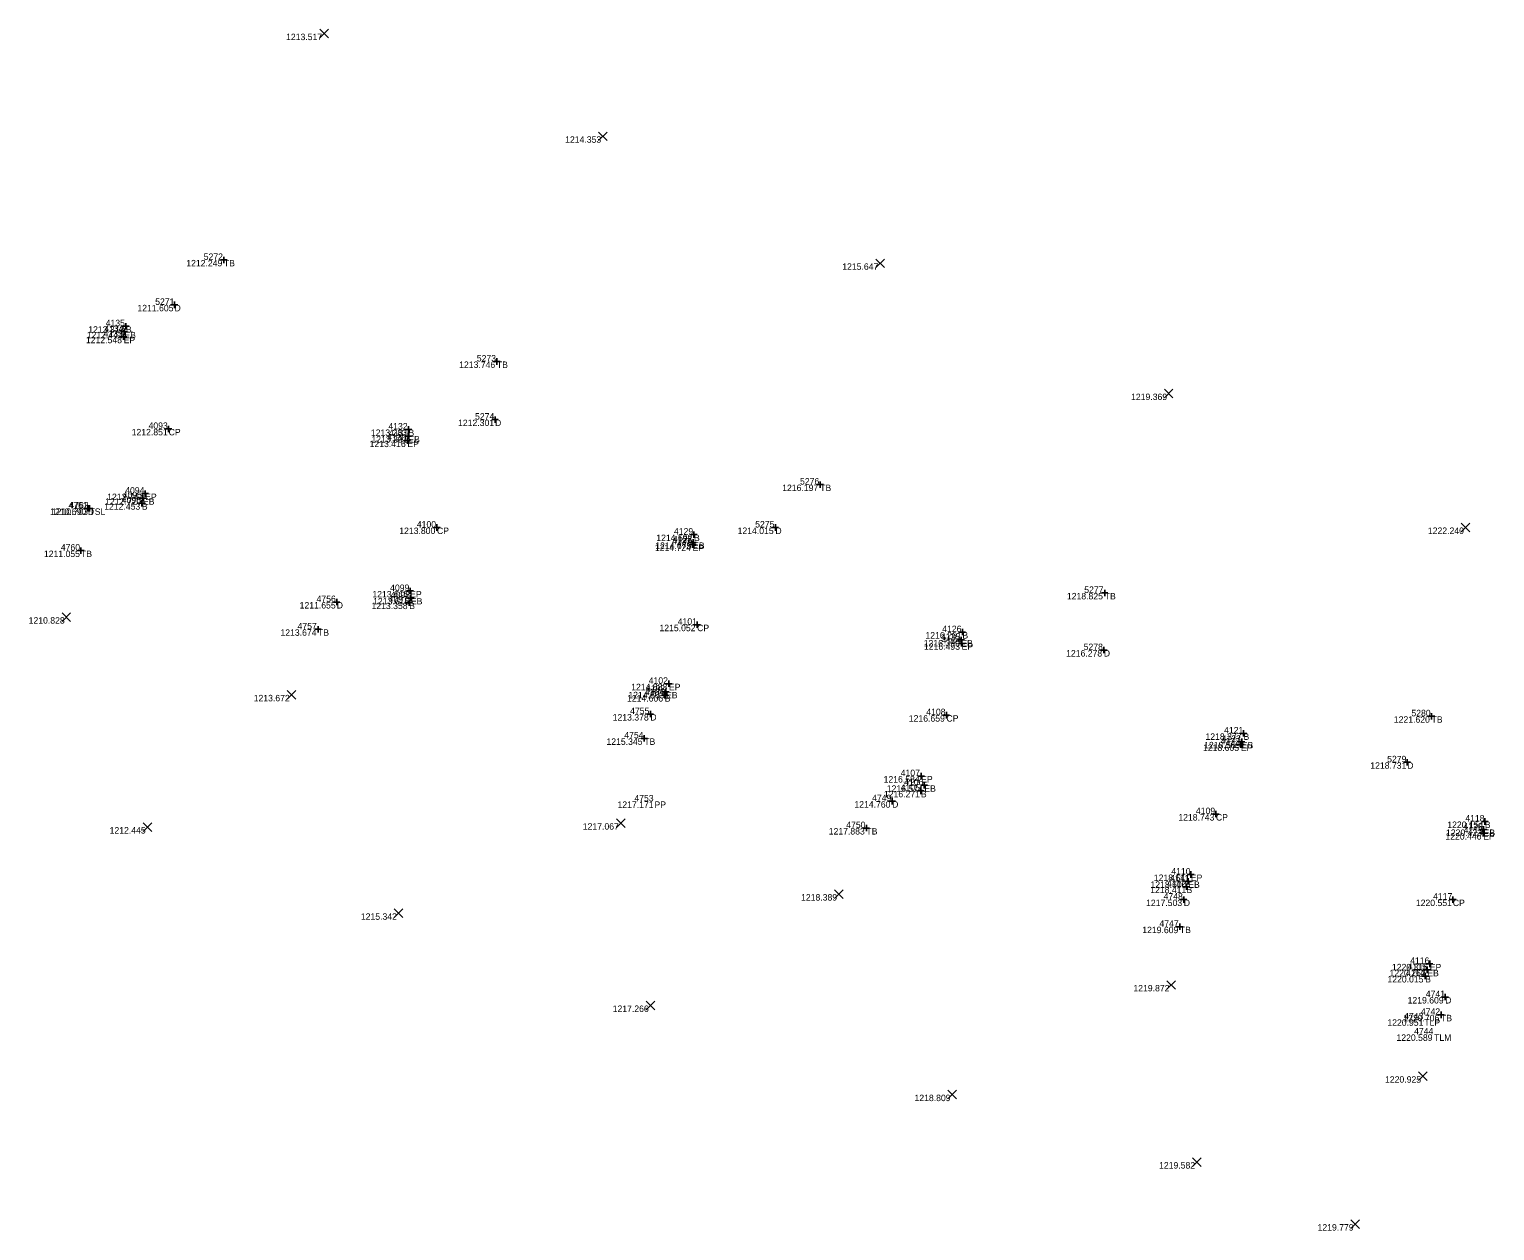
# Model space of a CAD drawing. Extents: x 2044997 to 2050342, y 455233 to 458054.
# Drawn here: x 2048396.8 to 2048623.5, y 456585.3 to 456771.2 of the extents above; entities that cross this region are included whole.
import ezdxf

# ---------------------------------------------------------------- set-up
doc = ezdxf.new("R2010")
doc.units = 0
for name, color, linetype in [('SV_X_Random_Point', 7, 'Continuous'), ('SV_X_Shot_Marker', 7, 'Continuous'), ('SV_X_Text_Comment', 7, 'Continuous'), ('SV_X_Text_Elevation', 7, 'Continuous'), ('SV_X_Text_Name', 7, 'Continuous')]:
    doc.layers.add(name, color=color, linetype=linetype)

msp = doc.modelspace()

# ---------------------------------------------------------------- linework, layer by layer
at = {"layer": 'SV_X_Random_Point'}
for p, q in [((2048441.72, 456769.84), (2048443.05, 456771.17)), ((2048441.72, 456771.17), (2048443.05, 456769.84)), ((2048484.85, 456753.95), (2048486.18, 456755.28)), ((2048484.85, 456755.28), (2048486.18, 456753.95)), ((2048527.78, 456734.31), (2048529.11, 456735.64)), ((2048527.78, 456735.64), (2048529.11, 456734.31)), ((2048572.4, 456714.15), (2048573.73, 456715.49)), ((2048572.4, 456715.49), (2048573.73, 456714.15)), ((2048618.34, 456693.45), (2048619.67, 456694.78)), ((2048618.34, 456694.78), (2048619.67, 456693.45)), ((2048401.85, 456679.57), (2048403.18, 456680.9)), ((2048401.85, 456680.9), (2048403.18, 456679.57)), ((2048436.67, 456667.55), (2048438, 456668.89)), ((2048436.67, 456668.89), (2048438, 456667.55)), ((2048487.63, 456647.71), (2048488.97, 456649.04)), ((2048487.63, 456649.04), (2048488.97, 456647.71)), ((2048414.39, 456647.1), (2048415.72, 456648.44)), ((2048414.39, 456648.44), (2048415.72, 456647.1)), ((2048521.35, 456636.73), (2048522.68, 456638.06)), ((2048521.35, 456638.06), (2048522.68, 456636.73)), ((2048453.24, 456633.77), (2048454.58, 456635.1)), ((2048453.24, 456635.1), (2048454.58, 456633.77)), ((2048572.78, 456622.68), (2048574.11, 456624.01)), ((2048572.78, 456624.01), (2048574.11, 456622.68)), ((2048492.21, 456619.5), (2048493.54, 456620.83)), ((2048492.21, 456620.83), (2048493.54, 456619.5)), ((2048611.72, 456608.56), (2048613.06, 456609.9)), ((2048611.72, 456609.9), (2048613.06, 456608.56)), ((2048538.89, 456605.71), (2048540.22, 456607.05)), ((2048538.89, 456607.05), (2048540.22, 456605.71)), ((2048576.74, 456595.28), (2048578.08, 456596.62)), ((2048576.74, 456596.62), (2048578.08, 456595.28)), ((2048601.25, 456585.68), (2048602.59, 456587.02)), ((2048601.25, 456587.02), (2048602.59, 456585.68))]:
    msp.add_line(p, q, dxfattribs=at)
at = {"layer": 'SV_X_Shot_Marker'}
for p, q in [((2048426.39, 456735.5), (2048427.39, 456735.5)), ((2048426.89, 456736), (2048426.89, 456735)), ((2048426.89, 456735.5), (2048426.89, 456735.5)), ((2048418.75, 456728.55), (2048419.75, 456728.55)), ((2048419.25, 456729.05), (2048419.25, 456728.05)), ((2048419.25, 456728.55), (2048419.25, 456728.55)), ((2048410.88, 456723.62), (2048411.88, 456723.62)), ((2048410.99, 456724.38), (2048411.99, 456724.38)), ((2048411.23, 456725.24), (2048412.23, 456725.24)), ((2048411.38, 456724.12), (2048411.38, 456723.12)), ((2048411.38, 456723.62), (2048411.38, 456723.62)), ((2048411.49, 456724.88), (2048411.49, 456723.88)), ((2048411.49, 456724.38), (2048411.49, 456724.38)), ((2048411.73, 456725.74), (2048411.73, 456724.74)), ((2048411.73, 456725.24), (2048411.73, 456725.24)), ((2048468.63, 456719.79), (2048469.63, 456719.79)), ((2048469.13, 456720.29), (2048469.13, 456719.29)), ((2048469.13, 456719.79), (2048469.13, 456719.79)), ((2048468.34, 456710.8), (2048469.34, 456710.8)), ((2048468.84, 456711.3), (2048468.84, 456710.3)), ((2048468.84, 456710.8), (2048468.84, 456710.8)), ((2048417.84, 456709.36), (2048418.84, 456709.36)), ((2048418.34, 456709.86), (2048418.34, 456708.86)), ((2048418.34, 456709.36), (2048418.34, 456709.36)), ((2048454.92, 456708.25), (2048455.92, 456708.25)), ((2048454.95, 456709.27), (2048455.95, 456709.27)), ((2048455.28, 456708.05), (2048455.28, 456707.05)), ((2048455.42, 456708.75), (2048455.42, 456707.75)), ((2048455.42, 456708.25), (2048455.42, 456708.25)), ((2048455.45, 456709.77), (2048455.45, 456708.77)), ((2048455.45, 456709.27), (2048455.45, 456709.27)), ((2048454.78, 456707.55), (2048455.78, 456707.55)), ((2048455.28, 456707.55), (2048455.28, 456707.55)), ((2048519.15, 456701.25), (2048519.15, 456700.25)), ((2048413.86, 456698.64), (2048414.86, 456698.64)), ((2048414.21, 456699.35), (2048415.21, 456699.35)), ((2048414.36, 456699.14), (2048414.36, 456698.14)), ((2048414.36, 456698.64), (2048414.36, 456698.64)), ((2048414.71, 456699.85), (2048414.71, 456698.85)), ((2048414.71, 456699.35), (2048414.71, 456699.35)), ((2048518.65, 456700.75), (2048519.65, 456700.75)), ((2048519.15, 456700.75), (2048519.15, 456700.75)), ((2048405.34, 456697.06), (2048406.34, 456697.06)), ((2048405.59, 456697.06), (2048406.59, 456697.06)), ((2048405.84, 456697.56), (2048405.84, 456696.56)), ((2048405.84, 456697.06), (2048405.84, 456697.06)), ((2048406.09, 456697.56), (2048406.09, 456696.56)), ((2048406.09, 456697.06), (2048406.09, 456697.06)), ((2048413.7, 456697.87), (2048414.7, 456697.87)), ((2048414.2, 456698.37), (2048414.2, 456697.37)), ((2048414.2, 456697.87), (2048414.2, 456697.87)), ((2048459.36, 456694.1), (2048460.36, 456694.1)), ((2048459.86, 456694.6), (2048459.86, 456693.6)), ((2048459.86, 456694.1), (2048459.86, 456694.1)), ((2048511.72, 456694.11), (2048512.72, 456694.11)), ((2048512.22, 456694.61), (2048512.22, 456693.61)), ((2048512.22, 456694.11), (2048512.22, 456694.11)), ((2048499.12, 456693.01), (2048500.12, 456693.01)), ((2048499.39, 456691.99), (2048499.39, 456690.99)), ((2048499.48, 456692.3), (2048499.48, 456691.3)), ((2048499.62, 456693.51), (2048499.62, 456692.51)), ((2048499.62, 456693.01), (2048499.62, 456693.01)), ((2048404.28, 456690.54), (2048405.28, 456690.54)), ((2048404.78, 456691.04), (2048404.78, 456690.04)), ((2048404.78, 456690.54), (2048404.78, 456690.54)), ((2048498.89, 456691.49), (2048499.89, 456691.49)), ((2048498.98, 456691.8), (2048499.98, 456691.8)), ((2048499.39, 456691.49), (2048499.39, 456691.49)), ((2048499.48, 456691.8), (2048499.48, 456691.8)), ((2048444.35, 456683.08), (2048444.35, 456682.08)), ((2048455.21, 456684.29), (2048456.21, 456684.29)), ((2048455.32, 456683.2), (2048456.32, 456683.2)), ((2048455.56, 456682.99), (2048455.56, 456681.99)), ((2048455.71, 456684.79), (2048455.71, 456683.79)), ((2048455.71, 456684.29), (2048455.71, 456684.29)), ((2048455.82, 456683.7), (2048455.82, 456682.7)), ((2048455.82, 456683.2), (2048455.82, 456683.2)), ((2048562.67, 456683.99), (2048563.67, 456683.99)), ((2048563.17, 456684.49), (2048563.17, 456683.49)), ((2048563.17, 456683.99), (2048563.17, 456683.99)), ((2048443.85, 456682.58), (2048444.85, 456682.58)), ((2048444.35, 456682.58), (2048444.35, 456682.58)), ((2048455.06, 456682.49), (2048456.06, 456682.49)), ((2048455.56, 456682.49), (2048455.56, 456682.49)), ((2048440.95, 456678.36), (2048441.95, 456678.36)), ((2048441.45, 456678.86), (2048441.45, 456677.86)), ((2048441.45, 456678.36), (2048441.45, 456678.36)), ((2048499.61, 456679.07), (2048500.61, 456679.07)), ((2048500.11, 456679.57), (2048500.11, 456678.57)), ((2048500.11, 456679.07), (2048500.11, 456679.07)), ((2048541.15, 456678.43), (2048541.15, 456677.43)), ((2048540.48, 456676.72), (2048541.48, 456676.72)), ((2048540.53, 456676.19), (2048541.53, 456676.19)), ((2048540.65, 456677.93), (2048541.65, 456677.93)), ((2048540.98, 456677.22), (2048540.98, 456676.22)), ((2048540.98, 456676.72), (2048540.98, 456676.72)), ((2048541.03, 456676.69), (2048541.03, 456675.69)), ((2048541.03, 456676.19), (2048541.03, 456676.19)), ((2048541.15, 456677.93), (2048541.15, 456677.93)), ((2048562.53, 456675.15), (2048563.53, 456675.15)), ((2048563.03, 456675.65), (2048563.03, 456674.65)), ((2048563.03, 456675.15), (2048563.03, 456675.15)), ((2048495.24, 456669.94), (2048496.24, 456669.94)), ((2048495.29, 456669.19), (2048495.29, 456668.19)), ((2048495.74, 456670.44), (2048495.74, 456669.44)), ((2048495.74, 456669.94), (2048495.74, 456669.94)), ((2048494.6, 456668.18), (2048495.6, 456668.18)), ((2048494.79, 456668.69), (2048495.79, 456668.69)), ((2048495.1, 456668.68), (2048495.1, 456667.68)), ((2048495.1, 456668.18), (2048495.1, 456668.18)), ((2048495.29, 456668.69), (2048495.29, 456668.69)), ((2048492.37, 456665.25), (2048493.37, 456665.25)), ((2048492.87, 456665.75), (2048492.87, 456664.75)), ((2048492.87, 456665.25), (2048492.87, 456665.25)), ((2048538.18, 456665.08), (2048539.18, 456665.08)), ((2048538.68, 456665.58), (2048538.68, 456664.58)), ((2048538.68, 456665.08), (2048538.68, 456665.08)), ((2048613.24, 456664.91), (2048614.24, 456664.91)), ((2048613.74, 456665.41), (2048613.74, 456664.41)), ((2048613.74, 456664.91), (2048613.74, 456664.91)), ((2048584.64, 456662.76), (2048584.64, 456661.76)), ((2048491.43, 456661.49), (2048492.43, 456661.49)), ((2048491.93, 456661.99), (2048491.93, 456660.99)), ((2048491.93, 456661.49), (2048491.93, 456661.49)), ((2048583.73, 456660.55), (2048584.73, 456660.55)), ((2048583.87, 456660.95), (2048584.87, 456660.95)), ((2048584.14, 456662.26), (2048585.14, 456662.26)), ((2048584.23, 456661.05), (2048584.23, 456660.05)), ((2048584.23, 456660.55), (2048584.23, 456660.55)), ((2048584.37, 456661.45), (2048584.37, 456660.45)), ((2048584.37, 456660.95), (2048584.37, 456660.95)), ((2048584.64, 456662.26), (2048584.64, 456662.26)), ((2048609.97, 456658.29), (2048609.97, 456657.29)), ((2048534.27, 456655.66), (2048535.27, 456655.66)), ((2048534.77, 456656.16), (2048534.77, 456655.16)), ((2048534.77, 456655.66), (2048534.77, 456655.66)), ((2048609.47, 456657.79), (2048610.47, 456657.79)), ((2048609.97, 456657.79), (2048609.97, 456657.79)), ((2048534.23, 456653.37), (2048535.23, 456653.37)), ((2048534.73, 456653.87), (2048534.73, 456652.87)), ((2048534.73, 456653.37), (2048534.73, 456653.37)), ((2048534.76, 456654.23), (2048535.76, 456654.23)), ((2048535.26, 456654.73), (2048535.26, 456653.73)), ((2048535.26, 456654.23), (2048535.26, 456654.23)), ((2048529.78, 456651.78), (2048530.78, 456651.78)), ((2048530.28, 456652.28), (2048530.28, 456651.28)), ((2048530.28, 456651.78), (2048530.28, 456651.78)), ((2048579.88, 456649.78), (2048580.88, 456649.78)), ((2048580.38, 456650.28), (2048580.38, 456649.28)), ((2048580.38, 456649.78), (2048580.38, 456649.78)), ((2048621.98, 456649.13), (2048621.98, 456648.13)), ((2048525.8, 456647.62), (2048526.8, 456647.62)), ((2048526.3, 456648.12), (2048526.3, 456647.12)), ((2048526.3, 456647.62), (2048526.3, 456647.62)), ((2048621.22, 456646.83), (2048622.22, 456646.83)), ((2048621.29, 456647.4), (2048622.29, 456647.4)), ((2048621.48, 456648.63), (2048622.48, 456648.63)), ((2048621.72, 456647.33), (2048621.72, 456646.33)), ((2048621.72, 456646.83), (2048621.72, 456646.83)), ((2048621.79, 456647.9), (2048621.79, 456646.9)), ((2048621.79, 456647.4), (2048621.79, 456647.4)), ((2048621.98, 456648.63), (2048621.98, 456648.63)), ((2048575.99, 456640.43), (2048576.99, 456640.43)), ((2048576.09, 456639.87), (2048576.09, 456638.87)), ((2048576.49, 456640.93), (2048576.49, 456639.93)), ((2048576.49, 456640.43), (2048576.49, 456640.43)), ((2048575.32, 456638.55), (2048576.32, 456638.55)), ((2048575.59, 456639.37), (2048576.59, 456639.37)), ((2048575.82, 456639.05), (2048575.82, 456638.05)), ((2048575.82, 456638.55), (2048575.82, 456638.55)), ((2048576.09, 456639.37), (2048576.09, 456639.37)), ((2048574.9, 456636.55), (2048575.9, 456636.55)), ((2048575.4, 456637.05), (2048575.4, 456636.05)), ((2048575.4, 456636.55), (2048575.4, 456636.55)), ((2048616.53, 456636.55), (2048617.53, 456636.55)), ((2048617.03, 456637.05), (2048617.03, 456636.05)), ((2048617.03, 456636.55), (2048617.03, 456636.55)), ((2048574.3, 456632.36), (2048575.3, 456632.36)), ((2048574.8, 456632.86), (2048574.8, 456631.86)), ((2048574.8, 456632.36), (2048574.8, 456632.36)), ((2048612.95, 456626.61), (2048613.95, 456626.61)), ((2048613.07, 456626.19), (2048613.07, 456625.19)), ((2048613.45, 456627.11), (2048613.45, 456626.11)), ((2048613.45, 456626.61), (2048613.45, 456626.61)), ((2048612.25, 456624.73), (2048613.25, 456624.73)), ((2048612.57, 456625.69), (2048613.57, 456625.69)), ((2048612.75, 456625.23), (2048612.75, 456624.23)), ((2048612.75, 456624.73), (2048612.75, 456624.73)), ((2048613.07, 456625.69), (2048613.07, 456625.69)), ((2048615.85, 456621.98), (2048615.85, 456620.98)), ((2048615.35, 456621.48), (2048616.35, 456621.48)), ((2048615.85, 456621.48), (2048615.85, 456621.48)), ((2048614.7, 456618.73), (2048615.7, 456618.73)), ((2048615.2, 456619.23), (2048615.2, 456618.23)), ((2048615.2, 456618.73), (2048615.2, 456618.73))]:
    msp.add_line(p, q, dxfattribs=at)

# ---------------------------------------------------------------- texts
at = {"layer": 'SV_X_Text_Comment'}
for s, p in [('TB', (2048426.89, 456734.5)), ('D', (2048419.25, 456727.55)), ('EP', (2048411.38, 456722.62)), ('EB', (2048411.49, 456723.38)), ('B', (2048411.73, 456724.24)), ('TB', (2048469.13, 456718.79)), ('D', (2048468.84, 456709.8)), ('CP', (2048418.34, 456708.36)), ('EB', (2048455.42, 456707.25)), ('B', (2048455.45, 456708.27)), ('EP', (2048455.28, 456706.55)), ('EB', (2048414.36, 456697.64)), ('EP', (2048414.71, 456698.35)), ('TB', (2048519.15, 456699.75)), ('D', (2048405.84, 456696.06)), ('TSL', (2048406.09, 456696.06)), ('B', (2048414.2, 456696.87)), ('CP', (2048459.86, 456693.1)), ('D', (2048512.22, 456693.11)), ('B', (2048499.62, 456692.01)), ('TB', (2048404.78, 456689.54)), ('EP', (2048499.39, 456690.49)), ('EB', (2048499.48, 456690.8)), ('EP', (2048455.71, 456683.29)), ('EB', (2048455.82, 456682.2)), ('TB', (2048563.17, 456682.99)), ('D', (2048444.35, 456681.58)), ('B', (2048455.56, 456681.49)), ('TB', (2048441.45, 456677.36)), ('CP', (2048500.11, 456678.07)), ('EB', (2048540.98, 456675.72)), ('EP', (2048541.03, 456675.19)), ('B', (2048541.15, 456676.93)), ('D', (2048563.03, 456674.15)), ('EP', (2048495.74, 456668.94)), ('B', (2048495.1, 456667.18)), ('EB', (2048495.29, 456667.69)), ('D', (2048492.87, 456664.25)), ('CP', (2048538.68, 456664.08)), ('TB', (2048613.74, 456663.91)), ('TB', (2048491.93, 456660.49)), ('EP', (2048584.23, 456659.55)), ('EB', (2048584.37, 456659.95)), ('B', (2048584.64, 456661.26)), ('EP', (2048534.77, 456654.66)), ('D', (2048609.97, 456656.79)), ('B', (2048534.73, 456652.37)), ('EB', (2048535.26, 456653.23)), ('PP', (2048493.51, 456650.74)), ('D', (2048530.28, 456650.78)), ('CP', (2048580.38, 456648.78)), ('TB', (2048526.3, 456646.62)), ('EP', (2048621.72, 456645.83)), ('EB', (2048621.79, 456646.4)), ('B', (2048621.98, 456647.63)), ('EP', (2048576.49, 456639.43)), ('B', (2048575.82, 456637.55)), ('EB', (2048576.09, 456638.37)), ('D', (2048575.4, 456635.55)), ('CP', (2048617.03, 456635.55)), ('TB', (2048574.8, 456631.36)), ('EP', (2048613.45, 456625.61)), ('B', (2048612.75, 456623.73)), ('EB', (2048613.07, 456624.69)), ('D', (2048615.85, 456620.48)), ('TLP', (2048612.61, 456617.03)), ('TB', (2048615.2, 456617.73)), ('TLM', (2048614.13, 456614.7))]:
    msp.add_text(s, height=1, dxfattribs=at).set_placement(p)
at = {"layer": 'SV_X_Text_Elevation'}
for s, p in [('1213.517', (2048436.51, 456769.5)), ('1214.353', (2048479.69, 456753.62)), ('1212.249', (2048421.07, 456734.5)), ('1215.647', (2048522.56, 456733.97)), ('1211.605', (2048413.51, 456727.55)), ('1212.548', (2048405.54, 456722.62)), ('1212.443', (2048405.67, 456723.38)), ('1212.313', (2048405.9, 456724.24)), ('1213.746', (2048463.29, 456718.79)), ('1219.369', (2048567.25, 456713.82)), ('1212.301', (2048463.12, 456709.8)), ('1212.851', (2048412.62, 456708.36)), ('1213.283', (2048449.63, 456708.27)), ('1213.391', (2048449.71, 456707.25)), ('1213.416', (2048449.44, 456706.55)), ('1212.720', (2048408.52, 456697.64)), ('1212.747', (2048408.83, 456698.35)), ('1216.197', (2048513.27, 456699.75)), ('1210.690', (2048400, 456696.06)), ('1210.703', (2048400.27, 456696.06)), ('1212.453', (2048408.37, 456696.87)), ('1213.800', (2048454.02, 456693.1)), ('1214.015', (2048506.37, 456693.11)), ('1222.240', (2048613.17, 456693.11)), ('1214.592', (2048493.79, 456692.01)), ('1211.055', (2048399.04, 456689.54)), ('1214.724', (2048493.58, 456690.49)), ('1214.675', (2048493.63, 456690.8)), ('1213.615', (2048449.86, 456683.29)), ('1213.615', (2048449.97, 456682.2)), ('1218.825', (2048557.32, 456682.99)), ('1211.655', (2048438.61, 456681.58)), ('1213.358', (2048449.73, 456681.49)), ('1210.828', (2048396.68, 456679.24)), ('1213.674', (2048435.64, 456677.36)), ('1215.052', (2048494.28, 456678.07)), ('1216.399', (2048535.17, 456675.72)), ('1216.493', (2048535.2, 456675.19)), ('1216.261', (2048535.43, 456676.93)), ('1216.278', (2048557.2, 456674.15)), ('1214.883', (2048489.91, 456668.94)), ('1213.672', (2048431.5, 456667.22)), ('1214.606', (2048489.26, 456667.18)), ('1214.803', (2048489.47, 456667.69)), ('1213.378', (2048487.04, 456664.25)), ('1216.659', (2048532.86, 456664.08)), ('1221.620', (2048607.9, 456663.91)), ('1215.345', (2048486.08, 456660.49)), ('1218.605', (2048578.38, 456659.55)), ('1218.569', (2048578.55, 456659.95)), ('1218.377', (2048578.76, 456661.26)), ('1216.584', (2048528.96, 456654.66)), ('1218.731', (2048604.26, 456656.79)), ('1216.271', (2048529.01, 456652.37)), ('1216.574', (2048529.45, 456653.23)), ('1217.171', (2048487.79, 456650.74)), ('1214.760', (2048524.44, 456650.78)), ('1218.743', (2048574.56, 456648.78)), ('1212.445', (2048409.21, 456646.77)), ('1217.067', (2048482.42, 456647.37)), ('1217.883', (2048520.47, 456646.62)), ('1220.446', (2048615.88, 456645.83)), ('1220.423', (2048615.97, 456646.4)), ('1220.154', (2048616.17, 456647.63)), ('1218.641', (2048570.77, 456639.43)), ('1218.389', (2048516.19, 456636.4)), ('1218.411', (2048570.21, 456637.55)), ('1218.600', (2048570.25, 456638.37)), ('1217.503', (2048569.57, 456635.55)), ('1220.551', (2048611.31, 456635.55)), ('1215.342', (2048448.08, 456633.43)), ('1219.609', (2048568.98, 456631.36)), ('1220.316', (2048607.61, 456625.61)), ('1220.015', (2048606.91, 456623.73)), ('1220.262', (2048607.24, 456624.69)), ('1219.872', (2048567.61, 456622.35)), ('1217.266', (2048487.04, 456619.17)), ('1219.609', (2048610.03, 456620.48)), ('1220.951', (2048606.9, 456617.03)), ('1220.706', (2048609.36, 456617.73)), ('1220.589', (2048608.31, 456614.7)), ('1220.925', (2048606.54, 456608.23)), ('1218.809', (2048533.74, 456605.38)), ('1219.582', (2048571.58, 456594.95)), ('1219.779', (2048596.1, 456585.35))]:
    msp.add_text(s, height=1, dxfattribs=at).set_placement(p)
at = {"layer": 'SV_X_Text_Name'}
for s, p in [('5272', (2048423.77, 456735.5)), ('5271', (2048416.26, 456728.55)), ('4135', (2048408.6, 456725.24)), ('4133', (2048408.27, 456723.62)), ('4134', (2048408.4, 456724.38)), ('5273', (2048466.02, 456719.79)), ('4093', (2048415.23, 456709.36)), ('4132', (2048452.34, 456709.27)), ('5274', (2048465.75, 456710.8)), ('4130', (2048452.16, 456707.55)), ('4131', (2048452.42, 456708.25)), ('5276', (2048516.03, 456700.75)), ('4096', (2048411.08, 456697.87)), ('4095', (2048411.23, 456698.64)), ('4094', (2048411.62, 456699.35)), ('4761', (2048402.84, 456697.06)), ('4762', (2048402.98, 456697.06)), ('4100', (2048456.74, 456694.1)), ('5275', (2048509.09, 456694.11)), ('4127', (2048496.23, 456691.49)), ('4128', (2048496.36, 456691.8)), ('4129', (2048496.52, 456693.01)), ('4760', (2048401.66, 456690.54)), ('4099', (2048452.61, 456684.29)), ('4756', (2048441.23, 456682.58)), ('4097', (2048452.4, 456682.49)), ('4098', (2048452.7, 456683.2)), ('5277', (2048560, 456683.99)), ('4757', (2048438.29, 456678.36)), ('4101', (2048497.11, 456679.07)), ('4126', (2048538.03, 456677.93)), ('4125', (2048537.85, 456676.72)), ('4124', (2048537.94, 456676.19)), ('5278', (2048559.91, 456675.15)), ('4104', (2048492.01, 456668.18)), ('4103', (2048492.18, 456668.69)), ('4102', (2048492.62, 456669.94)), ('4755', (2048489.74, 456665.25)), ('4108', (2048535.56, 456665.08)), ('5280', (2048610.62, 456664.91)), ('4754', (2048488.84, 456661.49)), ('4121', (2048581.64, 456662.26)), ('4122', (2048581.11, 456660.55)), ('4123', (2048581.26, 456660.95)), ('5279', (2048606.87, 456657.79)), ('4107', (2048531.61, 456655.66)), ('4105', (2048531.6, 456653.37)), ('4106', (2048532.14, 456654.23)), ('4753', (2048490.4, 456651.74)), ('4749', (2048527.18, 456651.78)), ('4109', (2048577.28, 456649.78)), ('4118', (2048618.96, 456648.63)), ('4750', (2048523.18, 456647.62)), ('4120', (2048618.67, 456647.4)), ('4119', (2048618.72, 456646.83)), ('4111', (2048573.3, 456639.37)), ('4110', (2048573.47, 456640.43)), ('4748', (2048572.28, 456636.55)), ('4112', (2048572.81, 456638.55)), ('4117', (2048613.97, 456636.55)), ('4747', (2048571.64, 456632.36)), ('4115', (2048610.05, 456625.69)), ('4116', (2048610.43, 456626.61)), ('4114', (2048609.77, 456624.73)), ('4741', (2048612.85, 456621.48)), ('4742', (2048612.09, 456618.73)), ('4743', (2048609.5, 456618.03)), ('4744', (2048611.04, 456615.7))]:
    msp.add_text(s, height=1, dxfattribs=at).set_placement(p)

doc.saveas('drawing.dxf')
